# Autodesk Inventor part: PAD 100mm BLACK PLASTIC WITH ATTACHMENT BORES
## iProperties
Created: 2007-03
Part Number: PAD 100mm BLACK PLASTIC WITH ATTACHMENT BORES
Document SubType Name: Modeling
Designer: Andy Moles
Material: ABS Plastic
Density: 1.06 g/cm^3
Mass: 119.714 g
Surface Area: 241.326 cm^2
Volume: 112.938 cm^3
Author: Andy Moles
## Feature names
1. Revolution1
2. Extrusion1
3. Extrusion2
4. Extrusion3
5. Fillet1
6. Extrusion4
